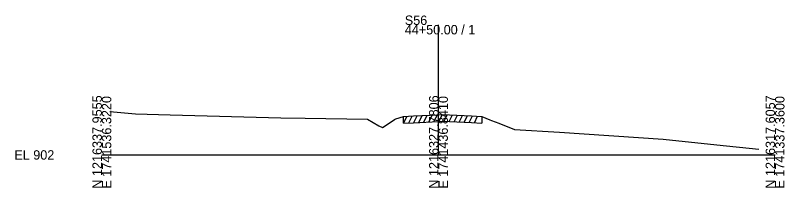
# Model space of a CAD drawing. Extents: x -26 to 1203, y -10 to 19541.
# Drawn here: x -25.7 to 202.8, y 19490.3 to 19541.4 of the extents above; entities that cross this region are included whole.
import ezdxf

# ---------------------------------------------------------------- set-up
doc = ezdxf.new("R2010")
doc.units = 0
for name, color, linetype in [('RD_GPK_XS_Cell', 7, 'Continuous'), ('RD_XS_ExGround', 7, 'Continuous'), ('RD_XS_ExPaveRet', 7, 'Continuous'), ('RD_XS_TX_Elev_EX', 7, 'Continuous')]:
    doc.layers.add(name, color=color, linetype=linetype)

msp = doc.modelspace()

# ---------------------------------------------------------------- linework, layer by layer
at = {"layer": 'RD_GPK_XS_Cell'}
for p, q in [((100, 19500), (100, 19538.58)), ((0, 19500), (100, 19500)), ((100, 19500), (200, 19500))]:
    msp.add_line(p, q, dxfattribs=at)
at = {"layer": 'RD_XS_ExGround'}
msp.add_lwpolyline([(2.34, 19512.86), (10.02, 19512.17), (20.27, 19511.86), (53.18, 19511.02), (60.38, 19510.92), (78.95, 19510.65), (82.29, 19508.61), (83.38, 19508.15), (84.12, 19508.6), (86.89, 19510.51), (87.37, 19510.67), (89.66, 19511.41), (92.57, 19511.58), (100, 19511.95), (101.14, 19512.01), (109.79, 19511.6), (112.84, 19511.46), (115.23, 19510.45), (115.79, 19510.2), (117.97, 19509.43), (122.63, 19507.55), (135.95, 19506.77), (166.76, 19504.65), (182.74, 19502.99), (195.21, 19501.68)], dxfattribs=at)
at = {"layer": 'RD_XS_ExPaveRet'}
for p, q in [((89.66, 19509.41), (90.69, 19511.47)), ((89.66, 19509.41), (89.66, 19511.41)), ((91.16, 19509.5), (92.19, 19511.56)), ((92.57, 19509.58), (100, 19509.95)), ((92.66, 19509.59), (93.68, 19511.64)), ((94.16, 19509.66), (95.18, 19511.71)), ((95.66, 19509.74), (96.68, 19511.79)), ((97.16, 19509.81), (98.18, 19511.86)), ((98.66, 19509.89), (99.68, 19511.94)), ((100, 19509.95), (101.14, 19510.01)), ((100.16, 19509.96), (101.18, 19512.01)), ((101.14, 19510.01), (109.79, 19509.6)), ((101.66, 19509.99), (102.63, 19511.94)), ((103.16, 19509.91), (104.13, 19511.87)), ((104.66, 19509.84), (105.63, 19511.8)), ((106.16, 19509.77), (107.13, 19511.72)), ((107.66, 19509.7), (108.63, 19511.65)), ((109.16, 19509.63), (110.13, 19511.58)), ((110.66, 19509.56), (111.63, 19511.51)), ((112.84, 19511.46), (112.84, 19509.46)), ((89.66, 19509.41), (92.57, 19509.58)), ((109.79, 19509.6), (112.84, 19509.46))]:
    msp.add_line(p, q, dxfattribs=at)

# ---------------------------------------------------------------- texts
at = {"layer": 'RD_GPK_XS_Cell'}
for s, p in [('S56', (90, 19538.58)), ('44+50.00 / 1', (90, 19535.78)), ('EL 902', (-26, 19498.6))]:
    msp.add_text(s, height=2.8, dxfattribs=at).set_placement(p)
for s, p in [('N 1216337.9555', (0, 19490)), ('E 1741536.3220', (2.8, 19490)), ('N 1216327.7806', (100, 19490)), ('E 1741436.8410', (102.8, 19490)), ('N 1216317.6057', (200, 19490)), ('E 1741337.3600', (202.8, 19490))]:
    msp.add_text(s, height=2.8, rotation=90, dxfattribs=at).set_placement(p)
at = {"layer": 'RD_XS_TX_Elev_EX'}
msp.add_text('907.98', height=0.1, rotation=90, dxfattribs=at).set_placement((100.1, 19511.95))

doc.saveas('drawing.dxf')
